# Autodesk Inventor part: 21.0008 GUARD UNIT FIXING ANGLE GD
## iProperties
Created: 2009-01
Part Number: 21.0008 GUARD UNIT FIXING ANGLE GD
Document SubType Name: Modeling
Designer: Administrator
Density: 2.71 g/cm^3
Material: Aluminum-6061
Mass: 20.5967 g
Surface Area: 41.4407 cm^2
Volume: 7.60027 cm^3
Author: Administrator
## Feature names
1. Base1
